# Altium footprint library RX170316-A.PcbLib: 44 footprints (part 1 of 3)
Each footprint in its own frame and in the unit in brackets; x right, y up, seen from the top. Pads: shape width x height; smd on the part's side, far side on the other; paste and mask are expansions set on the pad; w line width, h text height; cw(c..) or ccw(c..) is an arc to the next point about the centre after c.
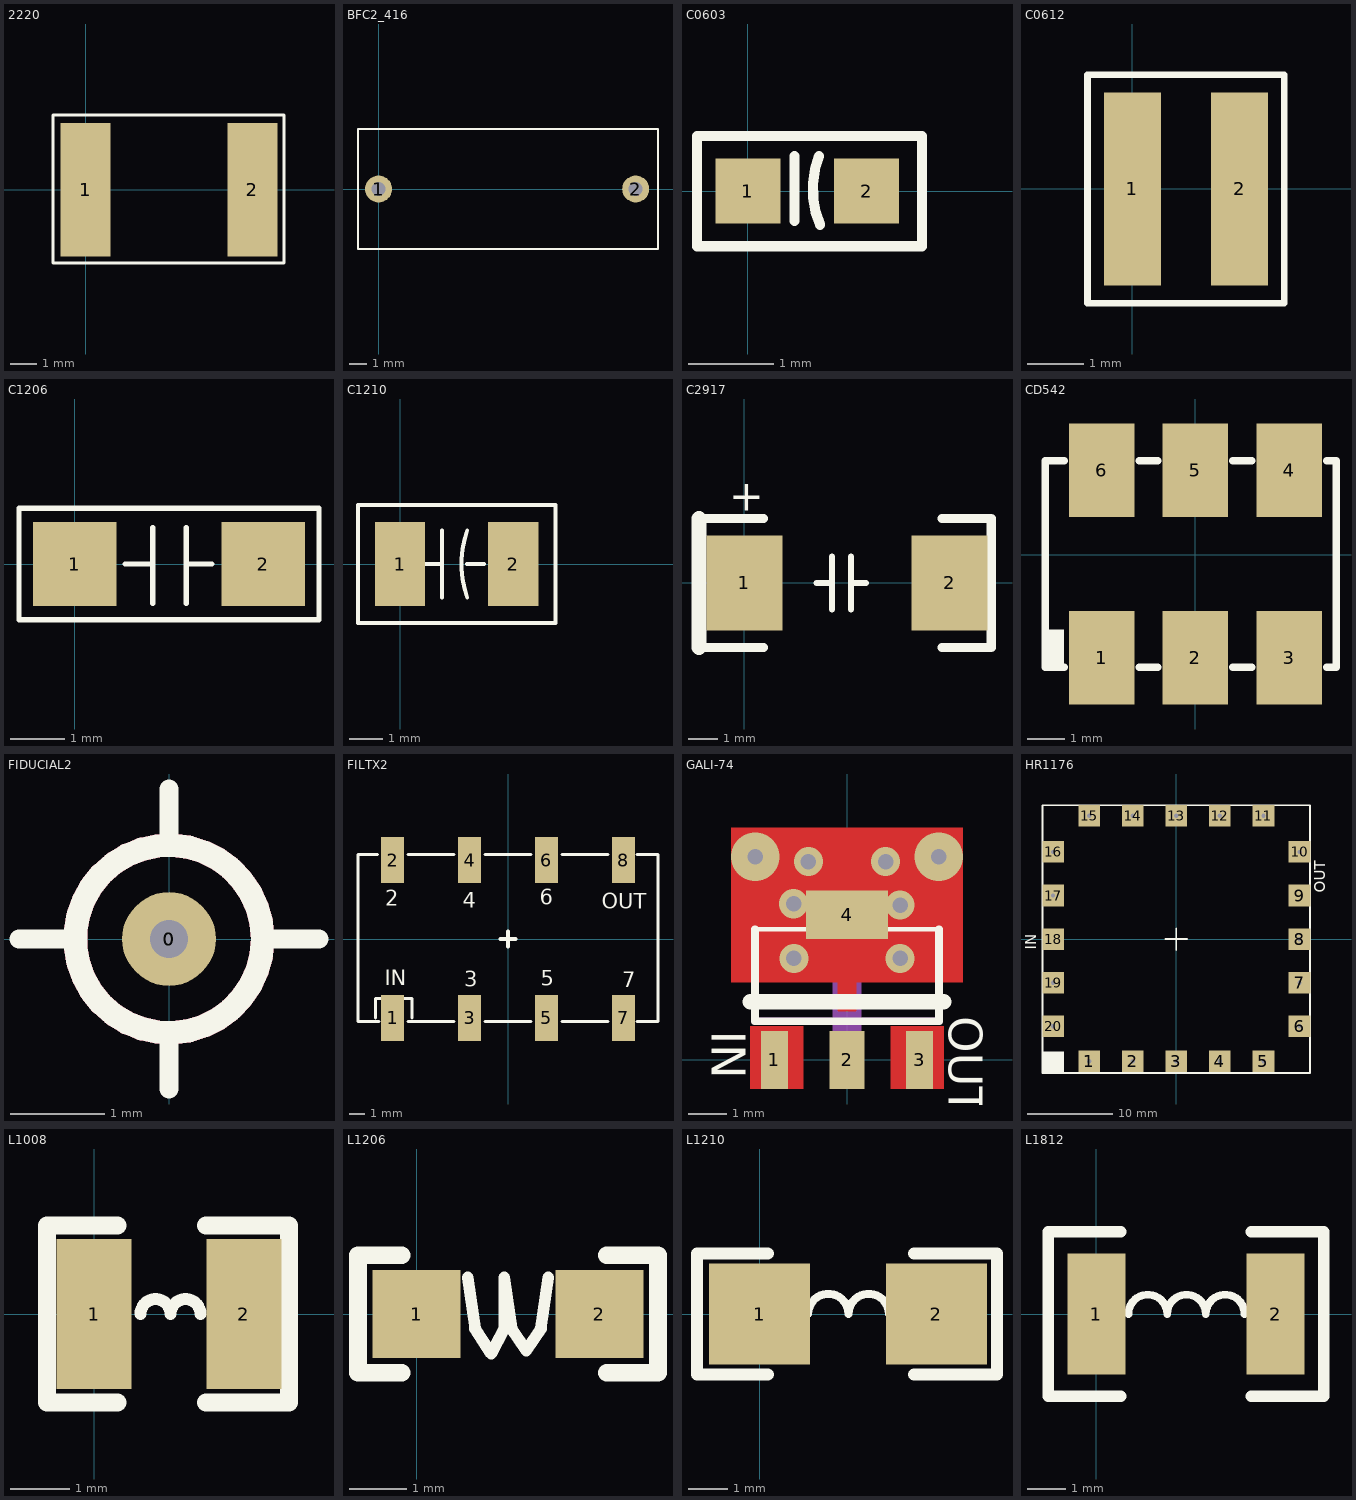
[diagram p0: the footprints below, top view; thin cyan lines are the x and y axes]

## 2220 [mil]
pads (2):
  rect 75x200 smd: 1(0,0) 2(250,0)
Top Overlay:
  lines w4.72: -49.21,-110.24 -49.21,112.2 297.24,112.2 297.24,-110.24 -49.21,-110.24

## BFC2_416 [mil]
pads (2):
  round 62 hole 32: 1(0,0) 2(590.55,0)
Top Overlay:
  lines w4.72: -47.24,-137.8 -47.24,137.8 641.73,137.8 641.73,-137.8 -47.24,-137.8

## C0603 [mil]
pads (2):
  rect 30x30 smd: 1(0,0) 2(55,0)
Top Overlay:
  lines w4.72: 21.65,-13.78 21.65,16.22 ; 32.91,16.25 ccw(c72.79,0.94) 33.46,-15.75 ; -23.62,-25.59 -23.62,25.59 80.71,25.59 80.71,-25.59 -23.62,-25.59

## C0612 [mil]
pads (2):
  rect 40x135 smd: 1(0,0) 2(75,0)
Top Overlay:
  lines w4.72: -31.5,-80 106.3,-80 106.3,80 -31.5,80 -31.5,-80
Top Paste:
  region: 93,65 57,65 57,-65 93,-65
  region: 18,65 -18,65 -18,-65 18,-65

## C1206 [mil]
pads (2):
  rect 60x60 smd: 1(0,0) 2(135,0)
Top Overlay:
  lines w3.94: 36,0 56,0 56,26 56,-28 ; 80,-28 80,26 80,0 98,0 ; -40,-40 175,-40 175,40 -40,40 -40,-40
Top Paste:
  region: 165,-30 165,30 105,30 105,-30
  region: 30,-30 30,30 -30,30 -30,-30

## C1210 [mil]
pads (2):
  rect 60x100 smd: 1(0,0) 2(135,0)
Top Overlay:
  lines w4.72: 30,0 50,0 ; 50,-40 50,40 ; 80.01,-40.03 cw(c190,0) 80.01,40.03 ; 80,0 100,0 ; -50,-70 185,-70 185,70 -50,70 -50,-70
Top Paste:
  region: 162,-48 162,48 108,48 108,-48
  region: 27,-48 27,48 -27,48 -27,-48

## C2917 [mil]
pads (2):
  rect 100x125 smd: 1(0,0) 2(270,0)
Top Overlay:
  lines w8: 95,0 115,0 ; 115,-35 115,35 ; 140,-35 140,35 ; 140,0 160,0
  lines w12: -60,-85 25,-85 ; -60,85 25,85 ; 260,-85 325,-85 325,85 260,85
  lines w20: -60,-85 -60,85
  text "+" at -20,95 h40
Top Paste:
  region: -48,61 -48,-61 48,-61 48,61
  region: 222,61 222,-61 318,-61 318,61

## CD542 [mil]
pads (6):
  rect 70x100 smd: 1(-100,-110) 2(0,-110) 3(100,-110) 4(100,90) 5(0,90) 6(-100,90)
Top Overlay:
  region: -160,-80 -160,-120 -140,-120 -140,-80
  lines w8: -140,-120 -160,-120 -160,100 -140,100 ; -60,-120 -40,-120 ; -60,100 -40,100 ; 40,-120 60,-120 ; 40,100 60,100 ; 140,-120 150,-120 150,100 140,100
Top Paste:
  region: -130,135 -130,45 -70,45 -70,135
  region: 70,-65 70,-155 130,-155 130,-65
  region: -30,-65 -30,-155 30,-155 30,-65
  region: -130,-65 -130,-155 -70,-155 -70,-65
  region: 70,135 70,45 130,45 130,135
  region: -30,135 -30,45 30,45 30,135

## FIDUCIAL2 [mm]
pads (3):
  round 2 on Top Solder: 0(0,0)
  round 2 on Bottom Solder: 0(0,0)
  round 1 hole 0.406: 0(0,0)
Top Layer:
  circle w0.25: c0,0 r1
Bottom Layer:
  circle w0.25: c0,0 r1
Top Overlay:
  circle w0.25: c0,0 r1
  lines w0.203: -1.6,0 -1.1,0 ; 0,-1.6 0,-1.1 ; 0,1.1 0,1.6 ; 1.1,0 1.6,0
Bottom Overlay:
  circle w0.25: c0,0 r1
  lines w0.203: -1.6,0 -1.1,0 ; 0,-1.6 0,-1.1 ; 0,1.1 0,1.6 ; 1.1,0 1.6,0

## FILTX2 [mil]
pads (8):
  rect 60x120 smd: 1(-300,-205) 2(-300,205) 3(-100,-205) 4(-100,205) 5(100,-205) 6(100,205) 7(300,-205) 8(300,205)
Top Overlay:
  lines w8: -345,-205 -345,-155 -250,-155 -250,-205 ; -340,220 -390,220 -390,-215 -335,-215 ; -260,-215 -140,-215 ; -260,220 -140,220 ; -60,-215 60,-215 ; -60,220 60,220 ; 140,-215 260,-215 ; 140,220 260,220 ; 335,-215 390,-215 390,220 335,220
  lines w10: -20,0 20,0 ; 0,-20 0,20
  text "2" at -318.9,86.61 h40
  text "4" at -118.11,80.71 h40
  text "6" at 82.68,88.58 h40
  text "3" at -114.17,-124.02 h40
  text "5" at 84.65,-122.05 h40
  text "7" at 297.24,-125.98 h40
  text "IN" at -320,-120 h40
  text "OUT" at 244.09,78.74 h40
Top Paste:
  region: -273,148 -273,262 -327,262 -327,148
  region: -73,148 -73,262 -127,262 -127,148
  region: 127,148 127,262 73,262 73,148
  region: 327,148 327,262 273,262 273,148
  region: 127,-262 127,-148 73,-148 73,-262
  region: 327,-262 327,-148 273,-148 273,-262
  region: -73,-262 -73,-148 -127,-148 -127,-262
  region: -273,-262 -273,-148 -327,-148 -327,-262

## GALI-74 [mil]
pads (4):
  rect 28x60 smd: 1(-75,0) 3(75,0)
  rect 36x60 smd: 2(0,0)
  rect 85x50 smd: 4(0,150)
via -55.12,161.42 diameter 30 hole 16
via -95,210 diameter 50 hole 16
via 95,210 diameter 50 hole 16
via 40,205 diameter 30 hole 16
via -55,105 diameter 30 hole 16
via 55,105 diameter 30 hole 16
via 55,160 diameter 30 hole 16
via -40,205 diameter 30 hole 16
Top Layer:
  region: 120,80 120,240 -120,240 -120,80
  region: 100,-30 100,35 45,35 45,-30
  region: -45,-30 -45,35 -100,35 -100,-30
  region: 10,50 10,115 -10,115 -10,50
Top Overlay:
  lines w5: -95,105 -95,135 -40,135 ; 40,135 95,135 95,105
  lines w8: -95,135 -95,40 95,40 95,135
  lines w16: -100,60 100,60
  text "IN" at -140,30 h35
  text "OUT" at 105,45 h35
Top Paste:
  region: 40,120 40,195 -40,195 -40,120
  region: 16,-28 16,28 -16,28 -16,-28
Top Solder:
  region: 40,80 40,205 -40,205 -40,80
  region: 10,15 10,175 -10,175 -10,15
  region: 100,-30 100,35 45,35 45,-30
  region: -45,-30 -45,35 -100,35 -100,-30
  region: 40,80 40,205 -40,205 -40,80
  region: 40,80 40,205 -40,205 -40,80
  region: 10,45 10,95 -10,95 -10,45
Mechanical 3:
  lines w8: -35,140 -25,160 25,160 35,140 ; -95,40 95,40 95,135 -95,135 -95,40
  lines w30: 0,0 0,149

## HR1176 [mil]
pads (20):
  rect 100x100 hole 20: 1(-404,-566) 2(-202,-566) 3(0,-566) 4(202,-566) 5(404,-566) 6(571,-404) 7(571,-202) 8(571,0) 10(571,404) 11(404,571) 12(202,571) 13(0,571) 14(-202,571) 15(-404,571) 16(-571,404) 17(-571,202) 19(-571,-202) 20(-571,-404)
  rect 100x100 smd: 9(571,202) 18(-571,0)
Top Overlay:
  region: -520,-620 -520,-520 -620,-520 -620,-620
  lines w8: -50,0 50,0 ; 0,-50 0,50 ; -620,-620 620,-620 620,620 -620,620 -620,-620
  text "OUT" at 690,215 h50
  text "IN" at -650,-50 h50
Top Paste:
  region: -523,-48 -523,48 -619,48 -619,-48
  region: -523,-250 -523,-154 -619,-154 -619,-250
  region: -523,-452 -523,-356 -619,-356 -619,-452
  region: -356,-614 -356,-518 -452,-518 -452,-614
  region: -154,-614 -154,-518 -250,-518 -250,-614
  region: 48,-614 48,-518 -48,-518 -48,-614
  region: 250,-614 250,-518 154,-518 154,-614
  region: 452,-614 452,-518 356,-518 356,-614
  region: 619,-452 619,-356 523,-356 523,-452
  region: 619,-250 619,-154 523,-154 523,-250
  region: 619,-48 619,48 523,48 523,-48
  region: 619,154 619,250 523,250 523,154
  region: 619,356 619,452 523,452 523,356
  region: 452,523 452,619 356,619 356,523
  region: 250,523 250,619 154,619 154,523
  region: 48,523 48,619 -48,619 -48,523
  region: -153,522 -153,618 -249,618 -249,522
  region: -356,523 -356,619 -452,619 -452,523
  region: -523,356 -523,452 -619,452 -619,356
  region: -523,154 -523,250 -619,250 -619,154

## L1008 [mil]
pads (2):
  rect 50x100 smd: 1(0,0) 2(100,0)
Top Overlay:
  lines w8: 31,0 cw(c41,0) 51,0 cw(c61,0) 71,0
  lines w12: 15.75,-59.06 -31.5,-59.06 -31.5,59.06 15.75,59.06 ; 74.8,-59.06 130,-59.06 130,59.06 74.8,59.06

## L1206 [mil]
pads (2):
  rect 60x60 smd: 1(0,0) 2(125,0)
Top Overlay:
  lines w8: 35,25 40,-10 51,-27 60,-10 60,25 65,-10 75,-25 85,-10 90,25
  lines w12: -10,-40 -40,-40 -40,40 -10,40 ; 130,-40 165,-40 165,40 130,40

## L1210 [mil]
pads (2):
  rect 100x100 smd mask+3: 1(0,0) 2(175,0)
Top Overlay:
  lines w8: 48,0 cw(c68,0) 88,0 cw(c108,0) 128,0
  lines w12: 7.98,-59.95 -62.02,-59.95 -62.02,60.05 7.98,60.05 ; 152.98,-59.95 235,-59.95 235,60.05 152.98,60.05

## L1812 [mil]
pads (2):
  rect 60x125 smd: 1(0,0) 2(185,0)
Top Overlay:
  lines w8: 33,0 cw(c53,0) 73,0 cw(c93,0) 113,0 cw(c133,0) 153,0
  lines w12: 25,-85 -50,-85 -50,85 25,85 ; 160,-85 235,-85 235,85 160,85
Top Paste:
  region: 210,-60 210,60 160,60 160,-60
  region: 25,-60 25,60 -25,60 -25,-60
